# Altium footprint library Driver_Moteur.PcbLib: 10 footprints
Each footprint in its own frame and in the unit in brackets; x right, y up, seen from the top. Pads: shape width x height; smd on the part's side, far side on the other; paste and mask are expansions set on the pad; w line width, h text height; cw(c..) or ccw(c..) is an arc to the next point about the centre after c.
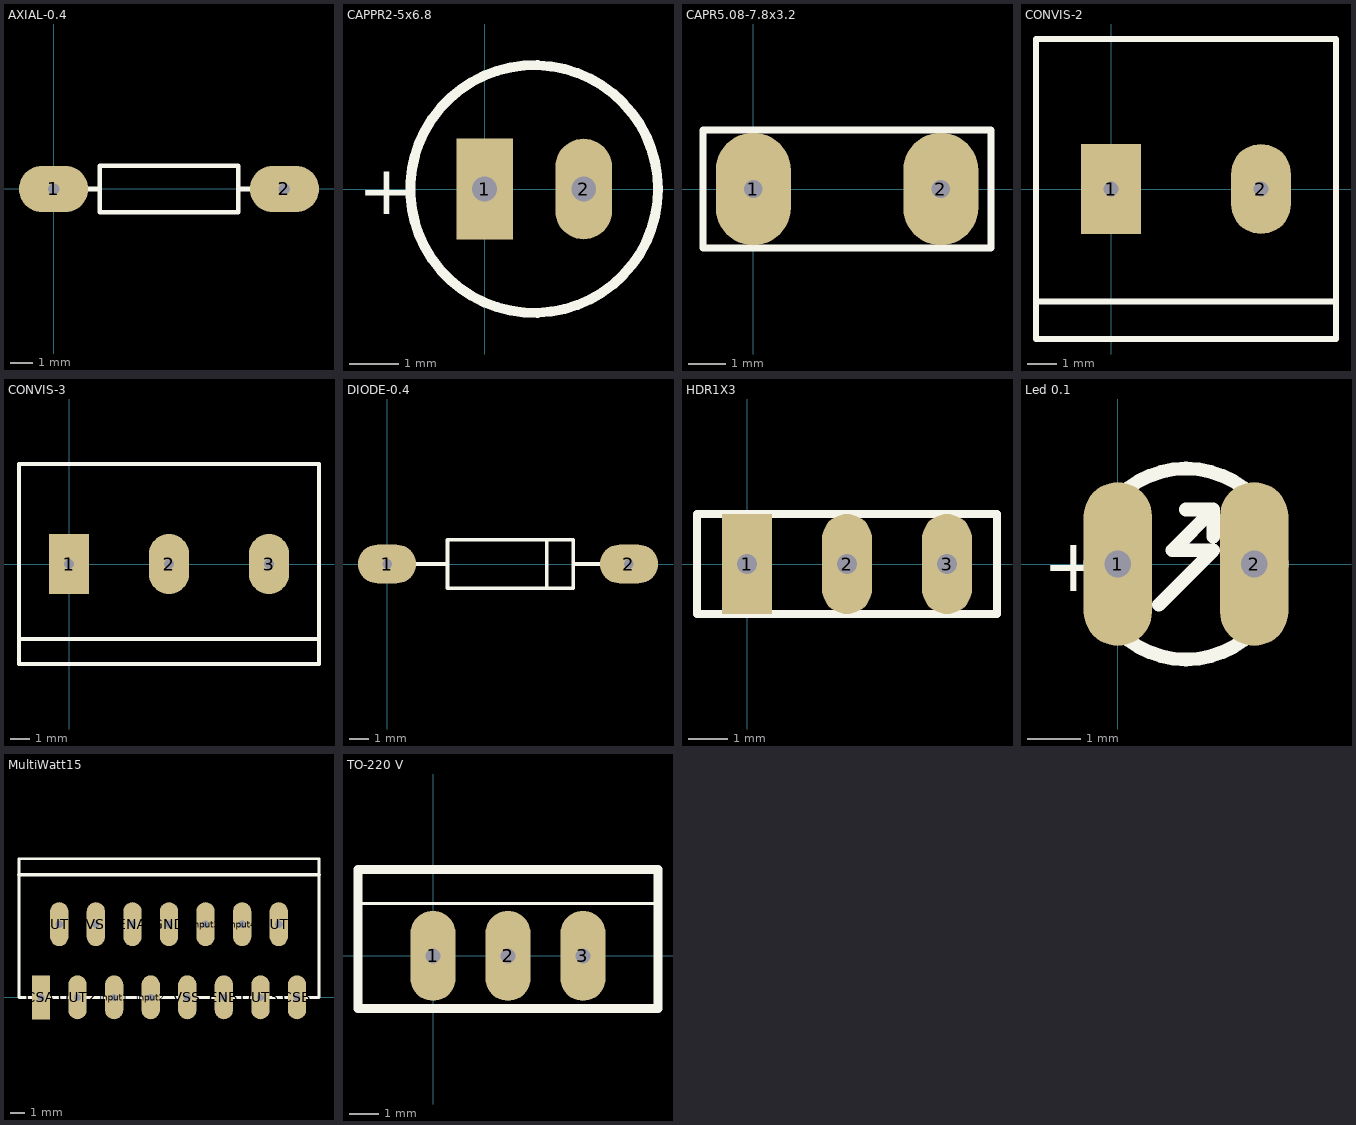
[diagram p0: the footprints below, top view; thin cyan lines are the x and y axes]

## AXIAL-0.4 [mil] "Resistor; 2 Leads"
height 80
pads (2):
  oval 120x80 hole 19.68 paste+0 mask+0: 1(0,0) 2(400,0)
Top Overlay:
  lines w7.87: 40,0 80,0 ; 320,0 360,0 ; 80,-40 320,-40 320,40 80,40 80,-40

## CAPPR2-5x6.8 [mil] "Capacitor, Electrolytic, Radial; Body 5 x 6.8 mm (Dia.xH typ); Pin Spacing 2 mm (typ)"
pads (2):
  rect 45x80 hole 19.68 paste+0 mask+0: 1(0,0)
  oval 45x80 hole 19.68 paste+0 mask+0: 2(78.74,0)
Top Overlay:
  circle w7.87: c39.37,0 r98.43
  text "+" at -100.63,-20 h39.37

## CAPR5.08-7.8x3.2 [mil] "Capacitor, Ceramic, Thru-Hole, Dipped Radial; Body 7.8 x 3.2 mm (WxT) Pin Spacing 5.08 mm (typ)"
height 236.22
pads (2):
  oval 80x120 hole 19.68 paste+0 mask+0: 1(0,0) 2(200,0)
Top Overlay:
  lines w7.87: -53.54,-62.99 253.54,-62.99 253.54,62.99 -53.54,62.99 -53.54,-62.99

## CONVIS-2 [mil] "Connecteur à vis 2 contacts Pitch 5.08"
height 590.55
pads (2):
  rect 80x120 hole 19.68 paste+0 mask+0: 1(0,0)
  oval 80x120 hole 19.68 paste+0 mask+0: 2(200,0)
Top Overlay:
  lines w8: -100,-150 300,-150 ; -100,-200 300,-200 300,200 100,200 -100,200 -100,-200

## CONVIS-3 [mil] "Connecteur à vis 3 contacts Pitch 5.08"
height 590.55
pads (3):
  rect 80x120 hole 19.68 paste+0 mask+0: 1(0,0)
  oval 80x120 hole 19.68 paste+0 mask+0: 2(200,0) 3(400,0)
Top Overlay:
  lines w8: -100,-150 500,-150 ; -100,-200 -100,200 500,200 500,-200 -100,-200

## DIODE-0.4 [mil] "Tunnel Diode - Dependent Source Model; 2 Leads"
height 100
pads (2):
  oval 120x80 hole 19.68 paste+0 mask+0: 1(0,0) 2(500,0)
Top Overlay:
  lines w7.87: 55,0 125,0 ; 330,-50 330,50 ; 385,0 500,0 ; 125,-50 385,-50 385,50 125,50 125,-50

## HDR1X3 [mm] "Connector; Header; 3 Position"
pads (3):
  rect 1.27x2.54 hole 0.5 paste+0 mask+0: 1(0,0)
  oval 1.27x2.54 hole 0.5 paste+0 mask+0: 2(2.54,0) 3(5.08,0)
Top Overlay:
  lines w0.2: -1.27,-1.27 -1.27,1.27 6.35,1.27 6.35,-1.27 -1.27,-1.27

## Led 0.1 [mil] "Led Verticale"
height 314.96
pads (2):
  oval 50x120 hole 19.68 paste+0 mask+0: 1(0,0) 2(100,0)
Top Overlay:
  circle w10: c50,0 r70
  lines w10: 30,-30 70,10 40,10 70,40 ; 50,40 70,40 ; 70,20 70,40
  text "+" at -55,-20 h39.37

## MultiWatt15 [mil] "MultiWatt15; 15 Leads; Row Spacing 5.08 mm; Pitch 2.54 mm"
height 200
pads (15):
  rect 50x120 hole 19.68 paste+0 mask+0: CSA(160,0)
  oval 50x120 hole 19.68 paste+0 mask+0: CSB(860,0) ENA(410,200) ENB(660,0) GND(510,200) input1(360,0) input2(460,0) input3(610,200) input4(710,200) OUT1(210,200) OUT2(260,0) OUT3(760,0) OUT4(810,200) VS(310,200) VSS(560,0)
Top Overlay:
  lines w7.87: 100,0 100,379 920,379 920,0 100,0
  lines w10: 100,335 920,335

## TO-220 V [mil] "TO-220 Vertical"
height 787.4
pads (3):
  oval 60x120 hole 19.68 paste+0 mask+0: 1(0,0) 2(100,0) 3(200,0)
Top Overlay:
  lines w4: -100,70 300,70
  lines w12: -100,-70 300,-70 300,70 300,115 -100,115 -100,70 -100,-70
